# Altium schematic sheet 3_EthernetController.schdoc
size 309 x 223 mm; Symbol: Sheet-Symbol_A4; Device: Sheet-Symbol_A4; @Project Name: ODrive Rev Motor Module; @Page Count: 5; @Update Date: 2024-10-18; @Create Date: 2024-10-18; @Schematic Name: Schematic-A; @Page No: 3; @Page Name: EthernetController; Company: EasyEDA.com; Reviewed: EasyEDA; Version: V0.1; Page Size: A4; Part Number: JLCPCB-002; Drawn: EasyEDA; @Board Name: BaseModule; @Create Time: 22:23:50; @Update Time: 18:23:52
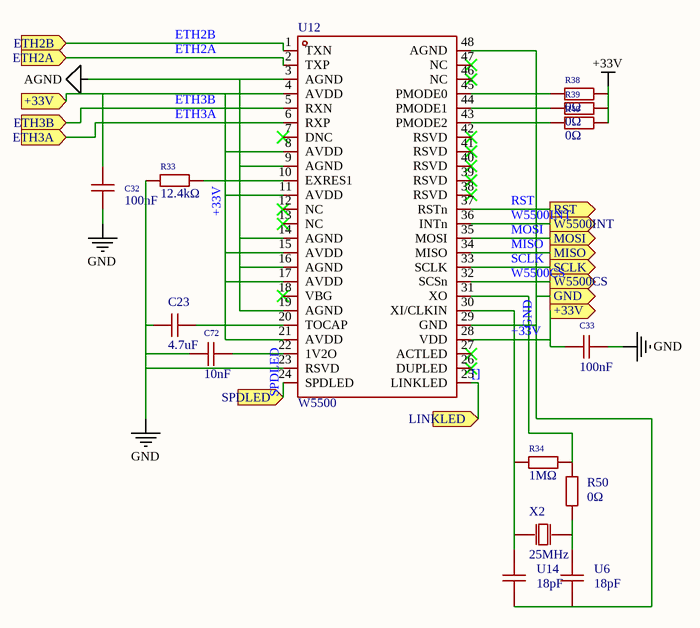
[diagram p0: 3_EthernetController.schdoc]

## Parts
C23  4.7uF  [C0603]  (value not drawn)
C32  100nF  [C0805]  (value not drawn)
C33  100nF  [C0805]  (value not drawn)
C72  10nF  [C0402]  (value not drawn)
R33  12.4kΩ  [R0402]  (value not drawn)
R34  1MΩ  [R1206]  (value not drawn)
R38  0Ω  [R0805]  (value not drawn)
R39  0Ω  [R0805]  (value not drawn)
R40  0Ω  [R0805]  (value not drawn)
R50  0Ω  [R0805]  (value not drawn)
U6  18pF  [C0201]  (value not drawn)
U12  W5500  [LQFP-48_L7.0-W7.0-P0.50-LS9.0-BL]  (value not drawn)
U14  18pF  [C0201]  (value not drawn)
X2  25MHz  [HC-49S_L11.4-W4.8]  (value not drawn)

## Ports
+33V (in), +33V (out), ETH2A (in), ETH2B (in), ETH3A (in), ETH3B (in), GND (out), LINKLED (in), MISO (out), MOSI (out), RST (out), SCLK (out), SPDLED (in), W5500CS (out), W5500INT (out)

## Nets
+33V: C32.1 C33.1 R38.2 R39.2 R40.2 U12.4(AVDD) U12.8(AVDD) U12.11(AVDD) U12.15(AVDD) U12.17(AVDD) U12.21(AVDD) U12.28(VDD) ; port +33V
AGND: U12.3(AGND) U12.9(AGND) U12.14(AGND) U12.16(AGND) U12.19(AGND)
GND: C23.1 C32.2 C33.2 C72.1 R33.1 U6.1 U12.23(RSVD) U12.29(GND) U12.48(AGND) U14.1 ; port GND
[]: U12.25(LINKLED) ; port LINKLED
ETH2A: U12.2(TXP) ; port ETH2A
ETH2B: U12.1(TXN) ; port ETH2B
ETH3A: U12.6(RXP) ; port ETH3A
ETH3B: U12.5(RXN) ; port ETH3B
MISO: U12.34(MISO) ; port MISO
MOSI: U12.35(MOSI) ; port MOSI
RST: U12.37(RSTn) ; port RST
SCLK: U12.33(SCLK) ; port SCLK
SPDLED: U12.24(SPDLED) ; port SPDLED
W5500CS: U12.32(SCSn) ; port W5500CS
W5500INT: U12.36(INTn) ; port W5500INT
NetC23_2: C23.2 U12.20(TOCAP)
NetC72_2: C72.2 U12.22(1V2O)
NetR33_2: R33.2 U12.10(EXRES1)
NetR34_1: R34.1 U12.30(XI/CLKIN) U14.2 X2.1(OSC1)
NetR34_2: R34.2 R50.2 U12.31(XO)
NetR38_1: R38.1 U12.45(PMODE0)
NetR39_1: R39.1 U12.44(PMODE1)
NetR40_1: R40.1 U12.43(PMODE2)
NetR50_1: R50.1 U6.2 X2.2(OSC2)

Not connected (* = marked no-connect by the designer): U12 7(DNC)* 12(NC)* 13(NC)* 18(VBG)* 26(DUPLED)* 27(ACTLED)* 38(RSVD)* 39(RSVD)* 40(RSVD)* 41(RSVD)* 42(RSVD)* 46(NC)* 47(NC)*

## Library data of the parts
C23 = CL10A475KQ8NNNC: Capacitance: Tolerance:±10% Tolerance:±10% Voltage Rated: Temperature Coefficient:; Manufacturer: SAMSUNG(三星); Add into BOM: yes; Tolerance: ±10%
C32 C33 = 0805B104K500NT: Capacitance:100nF Tolerance:±10% Tolerance:±10% Voltage Rated: Temperature Coefficient:; Manufacturer: FH(风华); Add into BOM: yes; Tolerance: ±10%
C72 = CC0402KRX7R9BB103: Capacitance: Tolerance:±10% Tolerance:±10% Voltage Rated: Temperature Coefficient:; Manufacturer: YAGEO(国巨); Add into BOM: yes; Tolerance: ±10%
R33 = 0402WGF1242TCE: Type:Thick Film Resistors Resistance:12.4kΩ Tolerance:±1% Tolerance:±1% Power(Watts): Overload Voltage (Max): Temperature Coefficient:±100ppm/℃ Temperature Coefficient:±100ppm/℃ Operating Temperature Range:-55℃~+155℃ Operating Temperature Range:-55℃~+155℃; Manufacturer: UNI-ROYAL(厚声); Add into BOM: yes; Tolerance: ±1%
R34 = 1206W4F1004T5E: Type:Thick Film Resistors Resistance:1MΩ Tolerance:±1% Tolerance:±1% Power(Watts): Overload Voltage (Max): Temperature Coefficient:±100ppm/℃ Temperature Coefficient:±100ppm/℃ Operating Temperature Range:-55℃~+155℃ Operating Temperature Range:-55℃~+155℃; Manufacturer: UNI-ROYAL(厚声); Add into BOM: yes; Tolerance: ±1%
R38-R40 = 0805W8F0000T5E_C17477: Type:Thick Film Resistors Resistance: Tolerance:±1% Tolerance:±1% Power(Watts): Overload Voltage (Max): Temperature Coefficient:±800ppm/℃ Temperature Coefficient:±800ppm/℃ Operating Temperature Range:-55℃~+155℃ Operating Temperature Range:-55℃~+155℃; Manufacturer: UNI-ROYAL(厚声); Add into BOM: yes; Tolerance: ±1%
R50 = RC0805JR-070RL: Type:Thick Film Resistors Resistance: Tolerance:±5% Tolerance:±5% Power(Watts): Overload Voltage (Max): Temperature Coefficient:- Temperature Coefficient:- Operating Temperature Range:-55℃~+155℃ Operating Temperature Range:-55℃~+155℃; Manufacturer: YAGEO(国巨); Add into BOM: yes; Tolerance: ±5%
U6 U14 = GJM0335C1E180GB01D: Capacitance: Tolerance:±2% Tolerance:±2% Voltage Rated: Temperature Coefficient:C0G; Manufacturer: muRata(村田); Add into BOM: yes; Tolerance: ±2%; Temperature Coefficient: C0G
U12 = W5500: Manufacturer: WIZNET; Add into BOM: yes
X2 = X49SM25MSD2SC: Crystal Type:Surface Mount Crystal Frequency: Normal temperature Frequency Tolerance:±20ppm Normal temperature Frequency Tolerance:±20ppm External load capacitor: Frequency Stability(Full temperature range):±30ppm Frequency Stability(Full temperature rang; Manufacturer: YXC(扬兴晶振); Add into BOM: yes; Normal temperature Frequency Tolerance: ±20ppm; Frequency Stability(Full temperature range): ±30ppm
